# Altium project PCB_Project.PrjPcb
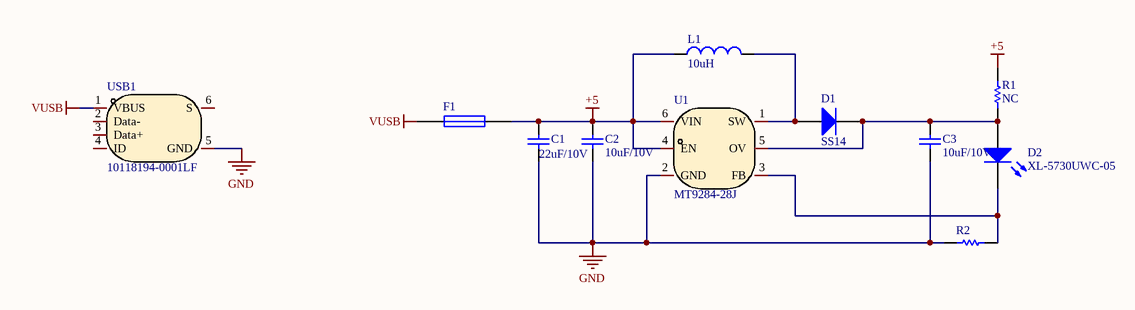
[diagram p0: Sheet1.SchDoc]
1 sheet, 11 parts. Net scope: global (net labels, ports and power ports of the same name join across sheets).
Board file: Copy of 231030 5630-112-20mm.PcbDoc

## Sheet Sheet1.SchDoc
size A4; SheetNumber: 1; SheetTotal: 1

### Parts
C1  22uF/10V  [0805-C]
C2  10uF/10V  [0805-C]
C3  10uF/10V  [0805-C]
D1  SS14  [SMA(DO-214AC)]
D2  XL-5730UWC-05  [LED-SMD_3P-L5.7-W3.0-RD]
F1  BSMD0805-050-24V  [0805-L]  (value not drawn)
L1  value 10uH  [IND-SMD_L4.0-W4.0]  (hidden comment: SWPA4030S100MT)
R1  NC  [0805-L]
R2  Res1  [0805-L]  (value not drawn)
U1  MT9284-28J  [SOT-23-6]
USB1  10118194-0001LF  [MICRO-USB-SMD]

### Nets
+5: C1.1 C2.2 F1.1 L1.1 R1.1 U1.4(EN) U1.6(VIN)
GND: C1.2 C2.1 C3.1 R2.1 U1.2(GND) USB1.5(GND)
VUSB: F1.2 USB1.1(VBUS)
NetC3_2: C3.2 D1.2(K) D2.1(A) R1.2 U1.5(OV)
NetD1_1: D1.1(A) L1.2 U1.1(SW)
NetD2_2: D2.2(K) R2.2 U1.3(FB)

Not connected (* = marked no-connect by the designer): USB1 2(Data-) 3(Data+) 4(ID) 6(S)

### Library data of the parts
C1 = Cap: 贴片电容
C2 C3 = Cap: Capacitor; Value: 100pF
D1 = Diode: Default Diode
D2 = LED1: LED-绿
F1 = Fuse 1
L1 = Inductor: Code_IEC: 1005
R1 R2 = Res1: Resistor; Value: 1K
